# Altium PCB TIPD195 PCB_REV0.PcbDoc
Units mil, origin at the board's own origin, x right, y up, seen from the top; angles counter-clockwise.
Board outline 1800 x 1800 mil, 2 copper layers (Top Layer, Bottom Layer); 32 components, 12 nets, 55 pads, 4 vias.
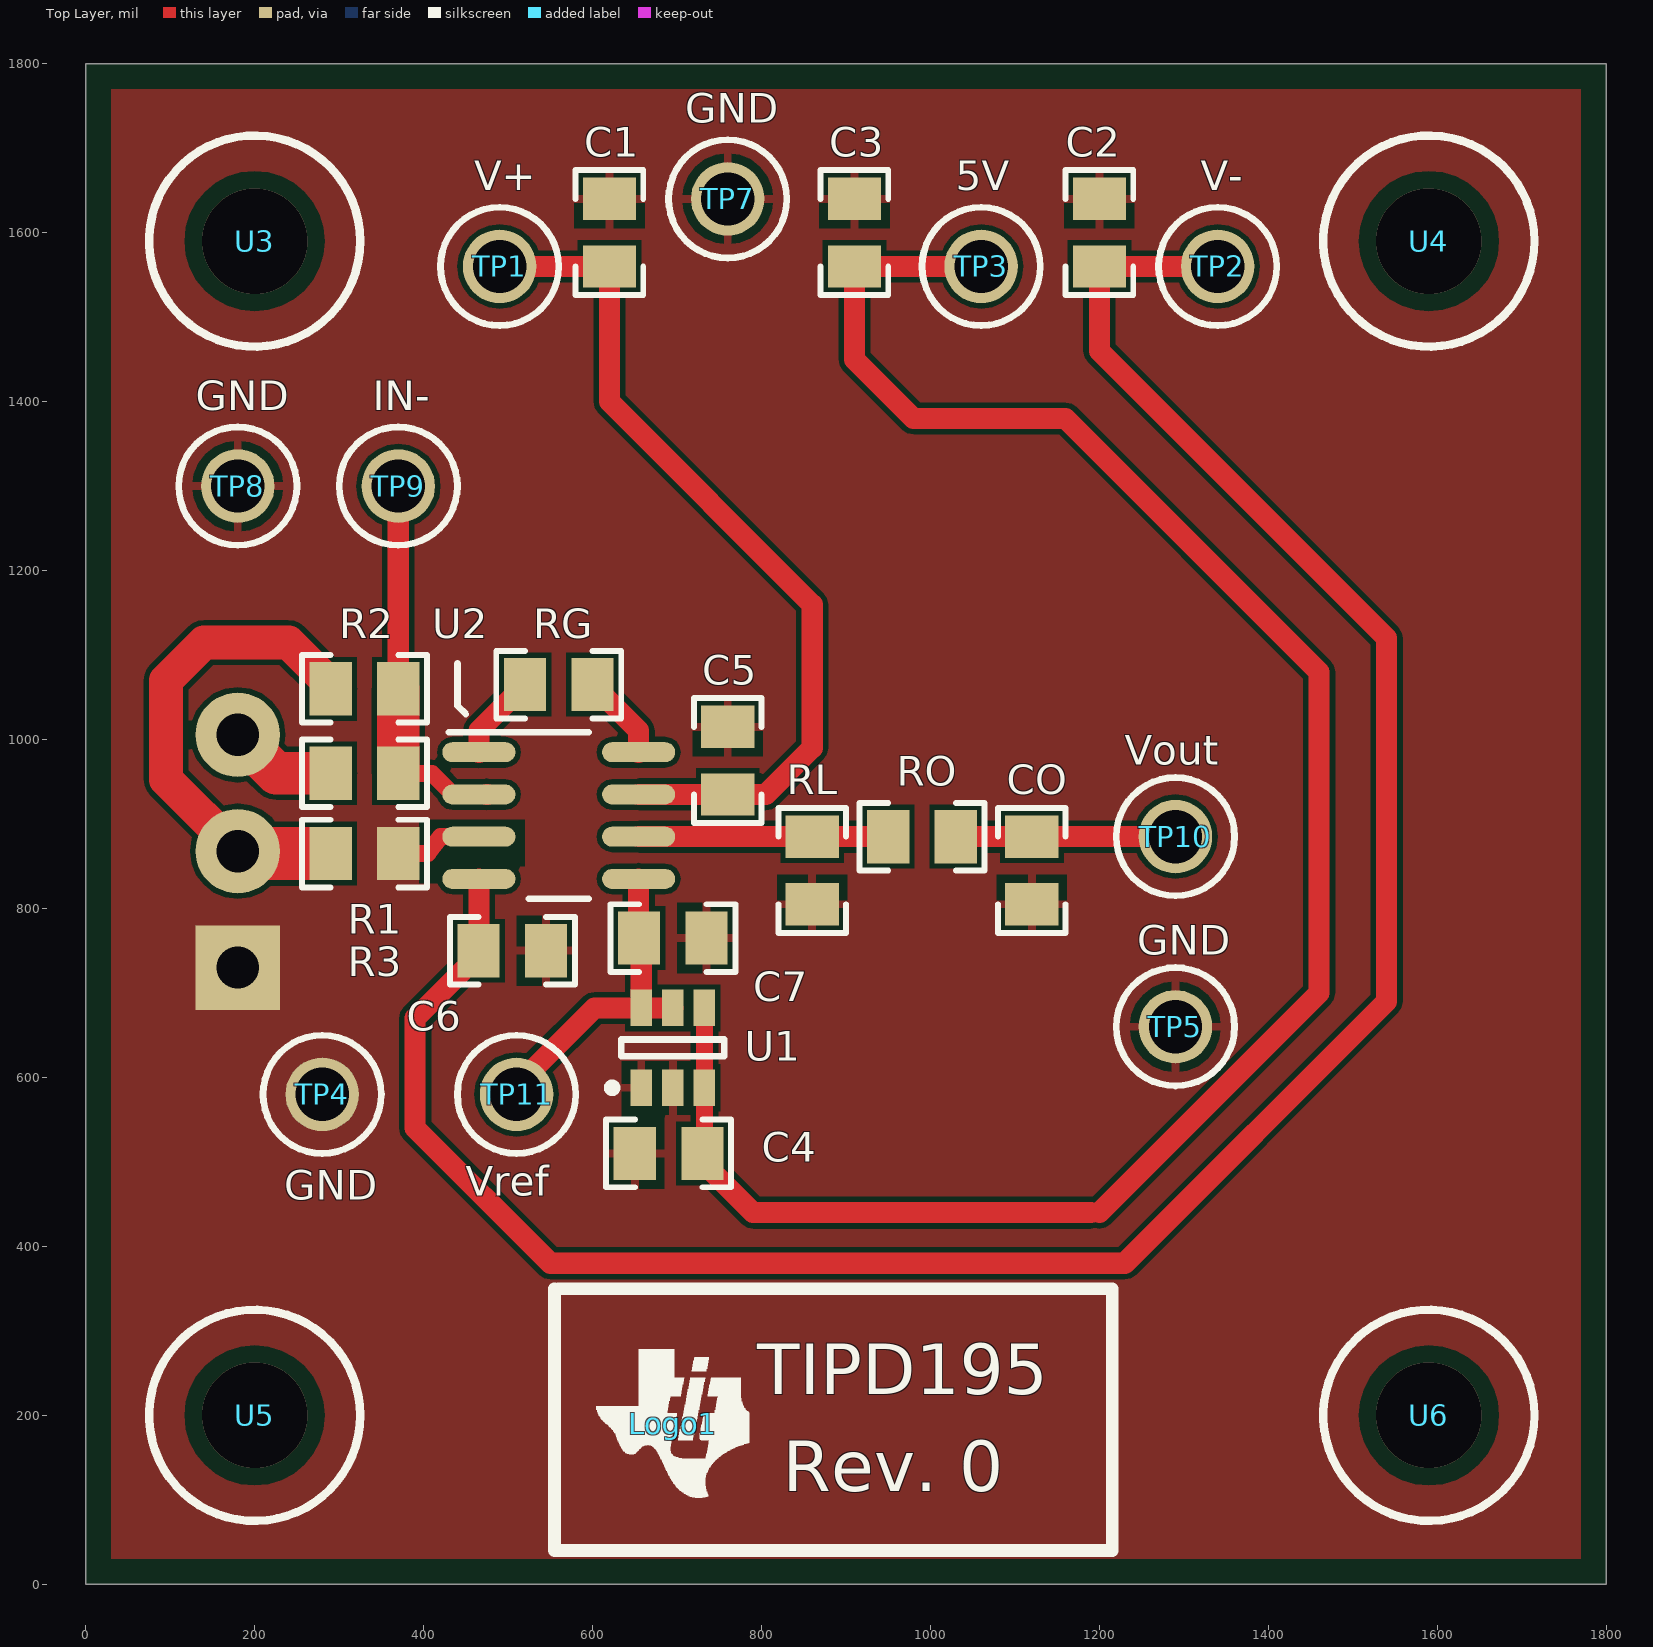
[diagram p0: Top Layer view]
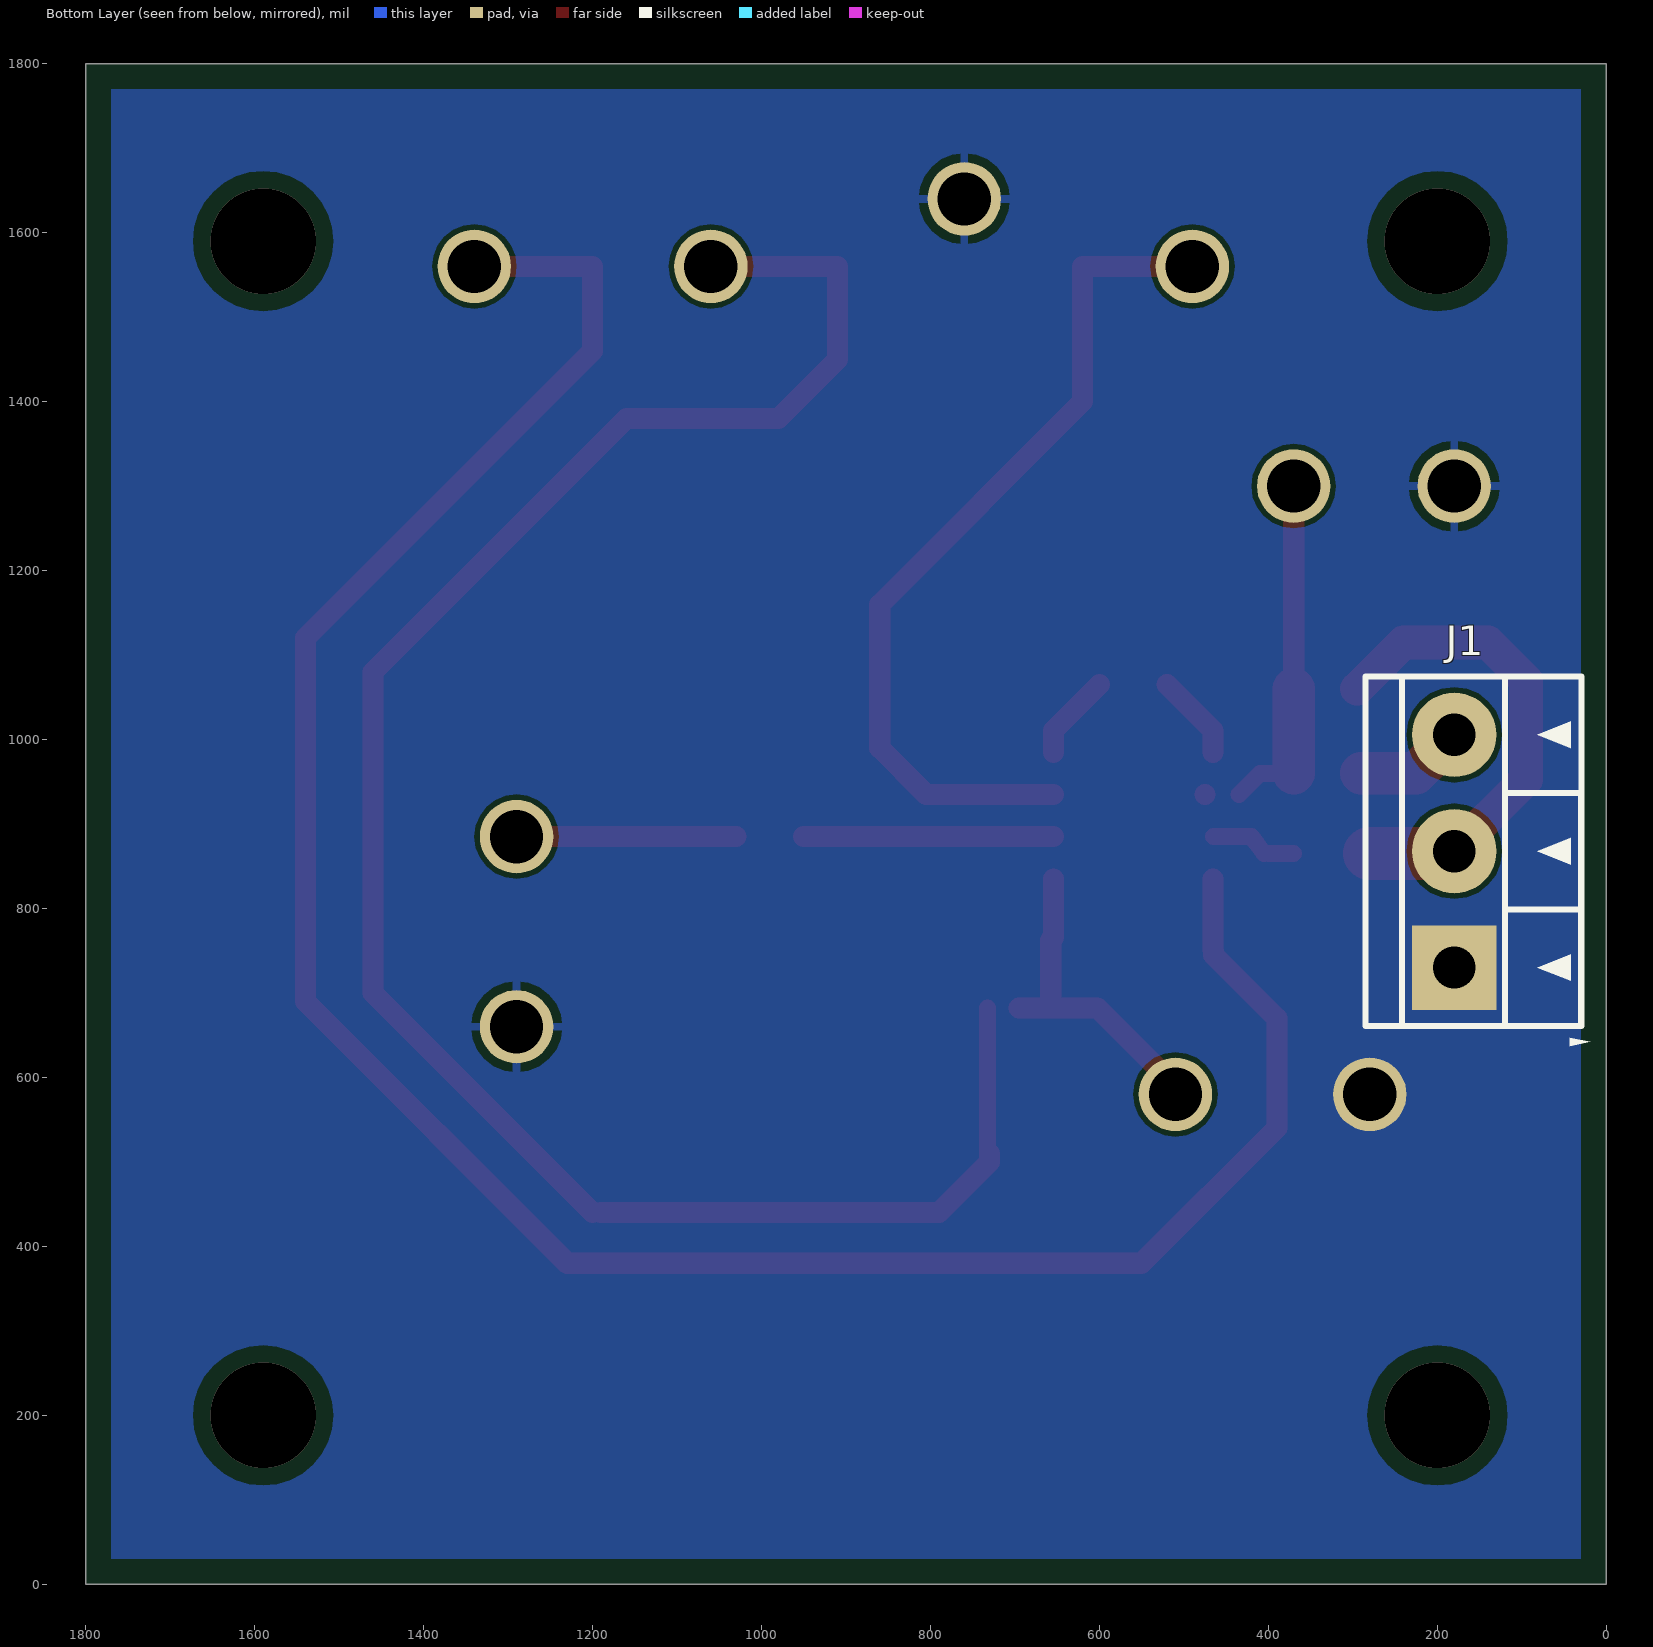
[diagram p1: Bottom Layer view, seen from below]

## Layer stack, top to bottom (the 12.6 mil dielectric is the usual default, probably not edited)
Top Solder: solder mask 0.4, Solder Resist, Dk 3.5
Top Layer: signal copper 1.4
Dielectric1: core 12.6, FR-4, Dk 4.8
Bottom Layer: signal copper 1.4
Bottom Solder: solder mask 0.4, Solder Resist, Dk 3.5

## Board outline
0,0 0,1800 1800,1800 1800,0

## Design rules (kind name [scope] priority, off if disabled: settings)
AssemblyTestPointUsage [All] p1 off:
AssemblyTestpoint [All] p1 off: testpointundercomponent=TRUE minsize=40 maxsize=100 preferedsize=60 minholesize=0 maxholesize=40 preferedholesize=32 testpointgrid=1 usegrid=TRUE gridtolerance=0.01 allowsidetop=TRUE allowsidebottom=TRUE
Clearance Clearance_1 [(HasFootprint('STANDOFF HEX 4-40THR ALUM 1"L'))] p1: gap=20
Clearance [All] p2: gap=6
ComponentClearance [All] p1 off: gap=10 collisioncheckmode=3 verticalgap=10 showdistances=FALSE
DiffPairsRouting [All] p1 off: maxlimit=10 minlimit=10 mostfreqgap=10 toplayer_minwidth=15 toplayer_maxwidth=15 toplayer_prefwidth=15 bottomlayer_minwidth=15 bottomlayer_maxwidth=15 bottomlayer_prefwidth=15 maxuncoupledlength=500
FabricationTestPointUsage TestPointUsage [All] p1 off: valid=0 allowmultiple=FALSE
FabricationTestpoint Testpoint [All] p1 off: side=3 testpointundercomponent=TRUE minsize=40 maxsize=100 preferedsize=60 minholesize=0 maxholesize=40 preferedholesize=32 testpointgrid=1 allowsidetop=TRUE allowsidebottom=TRUE usegrid=TRUE gridtolerance=0.01
FanoutControl Fanout_BGA [IsBGA] p1 off: bgadir=Out bgaviamode=Centered fanoutstyle=Auto fanoutdirection=Alternating viagrid=1 // Fanout_BGA (Default Rule)
FanoutControl Fanout_LCC [IsLCC] p2 off: bgadir=Out bgaviamode=Centered fanoutstyle=Auto fanoutdirection=Alternating viagrid=1 // Fanout_LCC (Default Rule)
FanoutControl Fanout_SOIC [IsSOIC] p3 off: bgadir=Out bgaviamode=Centered fanoutstyle=Auto fanoutdirection=Alternating viagrid=1 // Fanout_SOIC (Default Rule)
FanoutControl Fanout_Small [(CompPinCount < 5)] p4 off: bgadir=Out bgaviamode=Centered fanoutstyle=Auto fanoutdirection=OutThenIn viagrid=1 // Fanout_Small (Default Rule)
FanoutControl Fanout_Default [All] p5 off: bgadir=Out bgaviamode=Centered fanoutstyle=Auto fanoutdirection=Alternating viagrid=1 // Fanout_Default (Default Rule)
Height [All] p1 off: minheight=0 maxheight=1000 prefheight=500
HoleSize [All] p1: absolutevalues=TRUE maxlimit=400 minlimit=15 maxpercent=80.000 minpercent=20.000
HoleToHoleClearance [All] p1: gap=8 allowstackedmicrovias=TRUE
LayerPairs [All] p1 off: enforce=FALSE
MinimumSolderMaskSliver [All] p1: minsoldermaskwidth=4
PlaneClearance [All] p1: clearance=100
PolygonConnect PolygonConnect_1 [(InComponent('U2')  Or InComponent('R3')  Or  InComponent('J1')  Or  InComponent('TP4'))] p1: connectstyle=Direct reliefconductorwidth=25 reliefentries=4 polygonreliefangle="90 Angle" airgapwidth=10
PolygonConnect [All] p2: connectstyle=Relief reliefconductorwidth=10 reliefentries=4 polygonreliefangle="90 Angle" airgapwidth=10
RoutingVias [All] p1: holewidth=15 width=25 viastyle="Through Hole" minholewidth=15 minwidth=25 maxholewidth=400 maxwidth=500
SilkToSilkClearance [All] p1: silktosilkclearance=5
SilkToSolderMaskClearance SilkscreenOverComponentPads [IsPad] p1: minsilkscreentomaskgap=5 clearancetoexposedcopper=TRUE
SolderMaskExpansion [All] p1: expansion=2
UnpouredPolygon [All] p1: allowunpoured=FALSE
Width [All] p1: maxlimit=100 minlimit=6 preferedwidth=10
10 further rules are at their usual default settings.

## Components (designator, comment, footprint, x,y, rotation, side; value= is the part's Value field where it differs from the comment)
C1 "GRM21BR6YA106KE43L" 0805_HV 620,1600 r90 top
C2 "GRM21BR6YA106KE43L" 0805_HV 1200,1600 r90 top
C3 "GRM21BR6YA106KE43L" 0805_HV 910,1600 r90 top
C4 "TMK212BJ474KD-T" 0805_HV 690,510 r180 top
C5 "08055C104KAT2A" 0805_HV 760,975 r90 top
C6 "08055C104KAT2A" 0805_HV 505,750 r180 top
C7 "08055C104KAT2A" 0805_HV 695,765 r0 top
CO "CC0805KRX7R9BB332" 0805_HV 1120,845 r270 top
J1 "ED555/3DS" TERM_BLK_ED555-3DS 180,730 r90 bottom
Logo1 "Texas Instruments" TI_Symbol_Overlay_Small 695,190 r0 top
R1 "RG2012P-104-B-T5" 0805_HV 330,960 r180 top
R2 "RT0805BRD074K12L" 0805_HV 330,1060 r0 top
R3 "RP73PF2A20RBTDF" 0805_HV 330,865 r180 top
RG "RT0805BRD0710K7L" 0805_HV 560,1065 r180 top
RL "CRCW080510K0FKEA" 0805_HV 860,845 r90 top
RO "CRCW0805100RFKEA" 0805_HV 990,885 r0 top
TP1 "V+" Keystone5005 490,1560 r90 top
TP2 "V-" Keystone5009 1340,1560 r90 top
TP3 "5V" Keystone5008 1060,1560 r90 top
TP4 "GND" Keystone5006 280,580 r90 top
TP5 "GND" Keystone5006 1290,660 r90 top
TP7 "GND" Keystone5006 760,1640 r90 top
TP8 "GND" Keystone5006 180,1300 r90 top
TP9 "IN-" Keystone5122 370,1300 r90 top
TP10 "Vout" Keystone5122 1290,885 r90 top
TP11 "Vref" Keystone5122 510,580 r90 top
U1 "REF3225AIDBVT" DBV0006A_N 695,635 r90 top
U2 "INA188D" D0008A_N 560,910 r0 top
U3 "Standoff" "STANDOFF HEX 4-40THR ALUM 1\"L" 200,1590 r0 top
U4 "Standoff" "STANDOFF HEX 4-40THR ALUM 1\"L" 1590,1590 r0 top
U5 "Standoff" "STANDOFF HEX 4-40THR ALUM 1\"L" 200,200 r0 top
U6 "Standoff" "STANDOFF HEX 4-40THR ALUM 1\"L" 1590,200 r0 top

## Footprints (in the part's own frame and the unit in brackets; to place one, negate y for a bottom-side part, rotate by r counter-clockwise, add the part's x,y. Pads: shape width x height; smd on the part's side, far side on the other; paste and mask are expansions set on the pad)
0805_HV [mil] "0805 with 30mil clearance between pads"
  rect 50x63 smd: 1(-40,0) 2(40,0)
  silkscreen extent -74,-40 74,40, body extent -43,-29 43,29, height 43
D0008A_N [mm] "SOIC, 8-Leads, Body 4.9x3.9mm, Pitch 1.27mm, IPC Medium Density"
  oval 2.2x0.6 smd: 1(-2.4,1.905) 2(-2.4,0.635) 3(-2.4,-0.635) 4(-2.4,-1.905) 5(2.4,-1.905) 6(2.4,-0.635) 7(2.4,0.635) 8(2.4,1.905)
  silkscreen extent -3.3,-2.5 0.9,2.5, body extent -3,-2.45 3,2.45, height 1.63
DBV0006A_N [mm] "SOT23, 6-Leads, Body 2.9x1.6mm, Pitch 0.95mm, Lead Span 2.8mm, IPC Medium Density"
  rect 1.1x0.65 smd: 1(-1.2,0.95) 2(-1.2,0) 3(-1.2,-0.95) 4(1.2,-0.95) 5(1.2,0) 6(1.2,0.95)
  silkscreen extent -1.32,-1.55 0.25,1.95, body extent -1.42,-1.46 1.42,1.46, height 1.11
Keystone5005 [mil] "Keystone Compact loops"
  round 87 hole 63: 1(0,0)
  silkscreen extent -70,-70 70,70, body extent -63,-63 62,63, height 225
Keystone5006 [mil] "Keystone Compact loops"
  round 87 hole 63: 1(0,0)
  silkscreen extent -70,-70 70,70, body extent -63,-63 62,63, height 225
Keystone5008 [mil] "Keystone Compact loops"
  round 87 hole 63: 1(0,0)
  silkscreen extent -70,-70 70,70, body extent -63,-63 62,63, height 225
Keystone5009 [mil] "Keystone Compact loops"
  round 87 hole 63: 1(0,0)
  silkscreen extent -70,-70 70,70, body extent -63,-63 62,63, height 225
Keystone5122 [mil] "Keystone Compact loops"
  round 87 hole 63: 1(0,0)
  silkscreen extent -70,-70 70,70, body extent -63,-63 62,63, height 225
"STANDOFF HEX 4-40THR ALUM 1\"L" [mil] "STANDOFF HEX 4-40THR ALUM 1\"L"
  silkscreen extent -125,-125 125,125
TERM_BLK_ED555-3DS [mm]
  rect 2.54x2.54 hole 1.27: 1(0,0)
  round 2.54 hole 1.27: 2(3.5,0) 3(7,0)
  silkscreen extent -2.36,-4.09 8.75,2.67, body extent -1.75,-3.83 8.75,2.67, height 8.2
TI_Symbol_Overlay_Small [mil]
  silkscreen extent -90,-88 91,88

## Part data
C1 C2 C3: "CAP, CERM, 10 µF, 35 V, +/- 10%, X5R, 0805"
C4: "CAP, CERM, 0.47 µF, 20 V, +/- 10%, X5R, 0805"
C5 C6 C7: "CAP, CERM, 0.1 µF, 50 V, +/- 10%, X7R, 0805"
CO: "CAP, CERM, 3300 pF, 50 V, +/- 10%, X7R, 0805"
J1: "Terminal Block, 6A, 3.5mm Pitch, 3-Pos, TH"
Logo1: library part TI_Logo, "Texas Instrument Corporate Signature"
R1: "RES, 100 k, 0.1%, 0.125 W, 0805"
R2: "RES, 4.12 k, 0.1%, 0.125 W, 0805"
R3: "RES, 20.0, 0.1%, 0.25 W, 0805"
RG: "RES, 10.7 k, 0.1%, 0.125 W, 0805"
RL: "RES, 10.0 k, 1%, 0.125 W, 0805"
RO: "RES, 100, 1%, 0.125 W, 0805"
TP1: library part 5005, "Test Point, TH, Compact, Red"
TP2: library part 5009, "Test Point, Compact, Yellow, TH"
TP3: library part 5008, "Test Point, Compact, Orange, TH"
TP4 TP5 TP7 TP8: library part 5006, "Test Point, TH, Compact, Black"
TP9 TP10 TP11: library part 5122, "Test Point, Compact, Blue, TH"
U1: "2.5 V, 4 ppm / degC, 100 uA Series (Bandgap) Voltage Reference, -40 to 125 degC, 6-pin SOT-23 (DBV), Green (RoHS & no Sb/Br)"
U2: "INA188 Precision, Zero-Drift, Rail-to-Rail Out, High Voltage Instrumentation Amplifier, D0008A"
U3 U4 U5 U6: library part "Standoff, 1\", 4-40, Alum, F-F", "STANDOFF HEX 4-40THR ALUM 1\"L"

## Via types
v1: diameter 125, hole 125, Top Layer to Bottom Layer, 4 vias

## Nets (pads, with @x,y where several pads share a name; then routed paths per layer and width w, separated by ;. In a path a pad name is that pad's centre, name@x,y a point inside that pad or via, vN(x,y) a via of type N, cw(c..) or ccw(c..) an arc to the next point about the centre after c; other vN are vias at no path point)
5V: C3.1 C4.1 TP3.1 U1.3 U1.4 | length 2379
  Top Layer w20: C4.1 732.4,512.4 U1.3 U1.4
  Top Layer w25: C4.1 730,500 790,440 1190,440 ; TP3.1 C3.1 910,1450 980,1380 1160,1380 1460,1080 1460,700 1200,440
GND: C1.2 C2.2 C3.2 C4.2 C5.2 C6.1 C7.2 CO.2 J1.1 R3.1 RL.1 TP4.1 TP5.1 TP7.1 TP8.1 U1.1 U1.2 U2.3 | length 100
  Top Layer w20: R3.1 400,865 ; 405,865 420,885 U2.3@465,885
NetC7_1: C7.1 TP11.1 U1.5 U1.6 U2.5 | length 387.3
  Top Layer w25: TP11.1 510,590 602.24,682.24 U1.6 ; U2.5 654.49,765.51 C7.1 657.6,762.4 U1.6 ; U1.5 U1.6
NetCO_1: CO.1 RO.2 TP10.1 | length 260
  Top Layer w25: RO.2 CO.1 TP10.1
NetJ1_2: J1.2 R2.1 R3.2 | length 582.8
  Top Layer w25: R3.2@287.2,867.8 R3.2
  Top Layer w40: J1.2 95,952.8 95,1070 140,1115 240,1115 R2.1@295,1060
  Top Layer w63: J1.2@180,865 R3.2@280,865
NetJ1_3: J1.3 R1.2 | length 128.9
  Top Layer w50: J1.3 225.59,960 R1.2
NetR1_1: R1.1 R2.2 TP9.1 U2.2 | length 415.4
  Top Layer w20: R1.1 410,960 U2.2@435,935
  Top Layer w25: R2.2 TP9.1
  Top Layer w50: R1.1 R2.2
NetRG_1: RG.1 U2.8 | length 102.6
  Top Layer w25: RG.1 654.49,1010.51 U2.8
NetRG_2: RG.2 U2.1 | length 102.6
  Top Layer w25: U2.1 465.51,1010.51 RG.2
NetRL_2: RL.2 RO.1 U2.6 | length 295.5
  Top Layer w25: U2.6 RL.2 RO.1
V+: C1.1 C5.1 TP1.1 U2.7 | length 1027.7
  Top Layer w25: TP1.1 C1.1 620,1400 860,1160 860,990 805,935 C5.1 U2.7
V-: C2.1 C6.2 TP2.1 U2.4 | length 2821.8
  Top Layer w25: U2.4 465.51,750.51 C6.2 465,745 390,670 390,540 550,380 1230,380 1540,690 1540,1120 1200,1460 C2.1 TP2.1
copper on no net:
  other v1: 200,200 1590,200 200,1590 1590,1590

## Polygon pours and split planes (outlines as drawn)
GND on Top Layer "Top Layer-No Net" (solid, remove dead copper, pour order 2): 30,1770 1770,1770 1770,30 30,30
GND on Bottom Layer "Bottom Layer-No Net" (solid, remove dead copper, pour order 4): 30,1770 1770,1770 1770,30 30,30

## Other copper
Top Layer:
  pour cut-out: 395,830 420,830 420,850 520,850 520,905 395,905

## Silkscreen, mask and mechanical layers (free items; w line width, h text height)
Top Overlay:
  lines w8: 440,1090 440,1040 450,1030
  lines w15: 555,350 555,40 1215,40 1215,350 560,350
  text "TIPD195" at 795,225 h60
  text "Rev. 0" at 825,110 h60
Mechanical 1:
  the board outline again, w8

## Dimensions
0,0 to 1800,0 on Mechanical 2
0,0 to 0,1800 on Mechanical 2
